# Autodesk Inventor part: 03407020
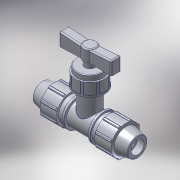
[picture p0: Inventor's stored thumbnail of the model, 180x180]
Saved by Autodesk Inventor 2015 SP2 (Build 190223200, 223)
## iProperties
Created: 2017-02
Part Number: 03407020
Material: PVC-Piping
Description: PLASSON COMPRESSION STOPTAP 20
Document SubType Name: Modeling
Designer: KIM
Mass: 92.6774 g
Surface Area: 199.44 cm^2
Volume: 66.1981 cm^3
Density: 1.4 g/cm^3
Appearance: PTFE
Author: KIM
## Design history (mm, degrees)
derived "03407.ipt"
feature "Solid1::03407.ipt"
tag "TaggingFeature1"
body "Solid1"
other parameters: "d1" = 147, "d4" = 12.25, "d5" = 17.64, "d7" = 48, "d8" = 36, "d9" = 36.75, "d11" = 3.675, "d12" = 38.4, "d13" = 120 deg, "d15" = 12 deg, "d16" = 43.2, "d18" = 1, "d19" = 35 deg, "d20" = 17.5 deg, "d21" = 44.64, "d23" = 0, "d25" = 360 deg, "d27" = 0.96, "d33" = 0.4, "d42" = 26.46, "d43" = 1.44, "d46" = 0.6, "d49" = 47, "d50" = 16, "d51" = 101, "d53" = 20.2, "d54" = 20.2, "d57" = 18.18, "d60" = 45.45, "d61" = 30.3, "d62" = 20.2, "d63" = 65.65, "d64" = 16.16, "d65" = 40.4, "d66" = 8.08, "d69" = 13.635, "d70" = 6.8175, "d71" = 44.541, "d72" = 41.4, "d74" = 0, "d75" = 17.17, "d76" = 92, "d77" = 92, "d80" = 360 deg, "d82" = 0.404, "d85" = 40.4, "d86" = 6 deg, "d87" = 94 deg, "d88" = 15.15, "d89" = 0, "d90" = 2, "d91" = 2, "d92" = 1.01, "d93" = 1.01, "E_" = 48, "H_" = 147, "l_" = 47, "A_" = 101, "d67" = 92, "d78" = 45.45
